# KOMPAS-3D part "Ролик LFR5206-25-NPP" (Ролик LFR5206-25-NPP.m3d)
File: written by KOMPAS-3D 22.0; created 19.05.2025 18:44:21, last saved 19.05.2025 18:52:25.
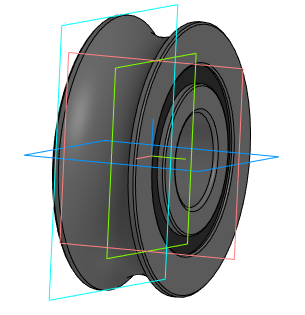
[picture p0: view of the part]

Document properties: Автор: user; Полное имя файла: D:\Работа\2025\5. Май\Задание №6 - Тележка для крыши\3Д\Ролик LFR5206-25-NPP.m3d

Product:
- Part/product: Ролик LFR5206-25-NPP
    Масса: 0.442345
    Раздел спецификации: Прочие изделия

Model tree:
1. Эскиз:1
2. Элемент выдавливания:1
     Расстояние 1 = 23.8
3. Эскиз:2
4. Элемент вращения:1
     Угол 1 = 360
5. Эскиз:3
6. Элемент выдавливания:2
     Расстояние 1 = 25.8
7. Смещенная плоскость:1  (with: Элемент выдавливания:1)
     Расстояние = 1
8. Эскиз:4  (with: Элемент выдавливания:1)
9. Элемент выдавливания:3
     Расстояние 2 = 1
10. Зеркальный массив:1
11. Экземпляр ( 1 )
12. Экземпляр ( 2 )  (with: Элемент выдавливания:3)
13. Скругление:1  (with: Элемент выдавливания:2, Элемент выдавливания:1)
     Радиус = 0.5
14. Фаска:1  (with: Элемент выдавливания:1)
     Угол = 45; Длина 1 = 0.5; Длина 2 = 0.5
15. Скругление:2  (with: Элемент выдавливания:2)
     Радиус = 1

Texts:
  Точка начала. Х
  Точка начала. Y
  Точка начала. Z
